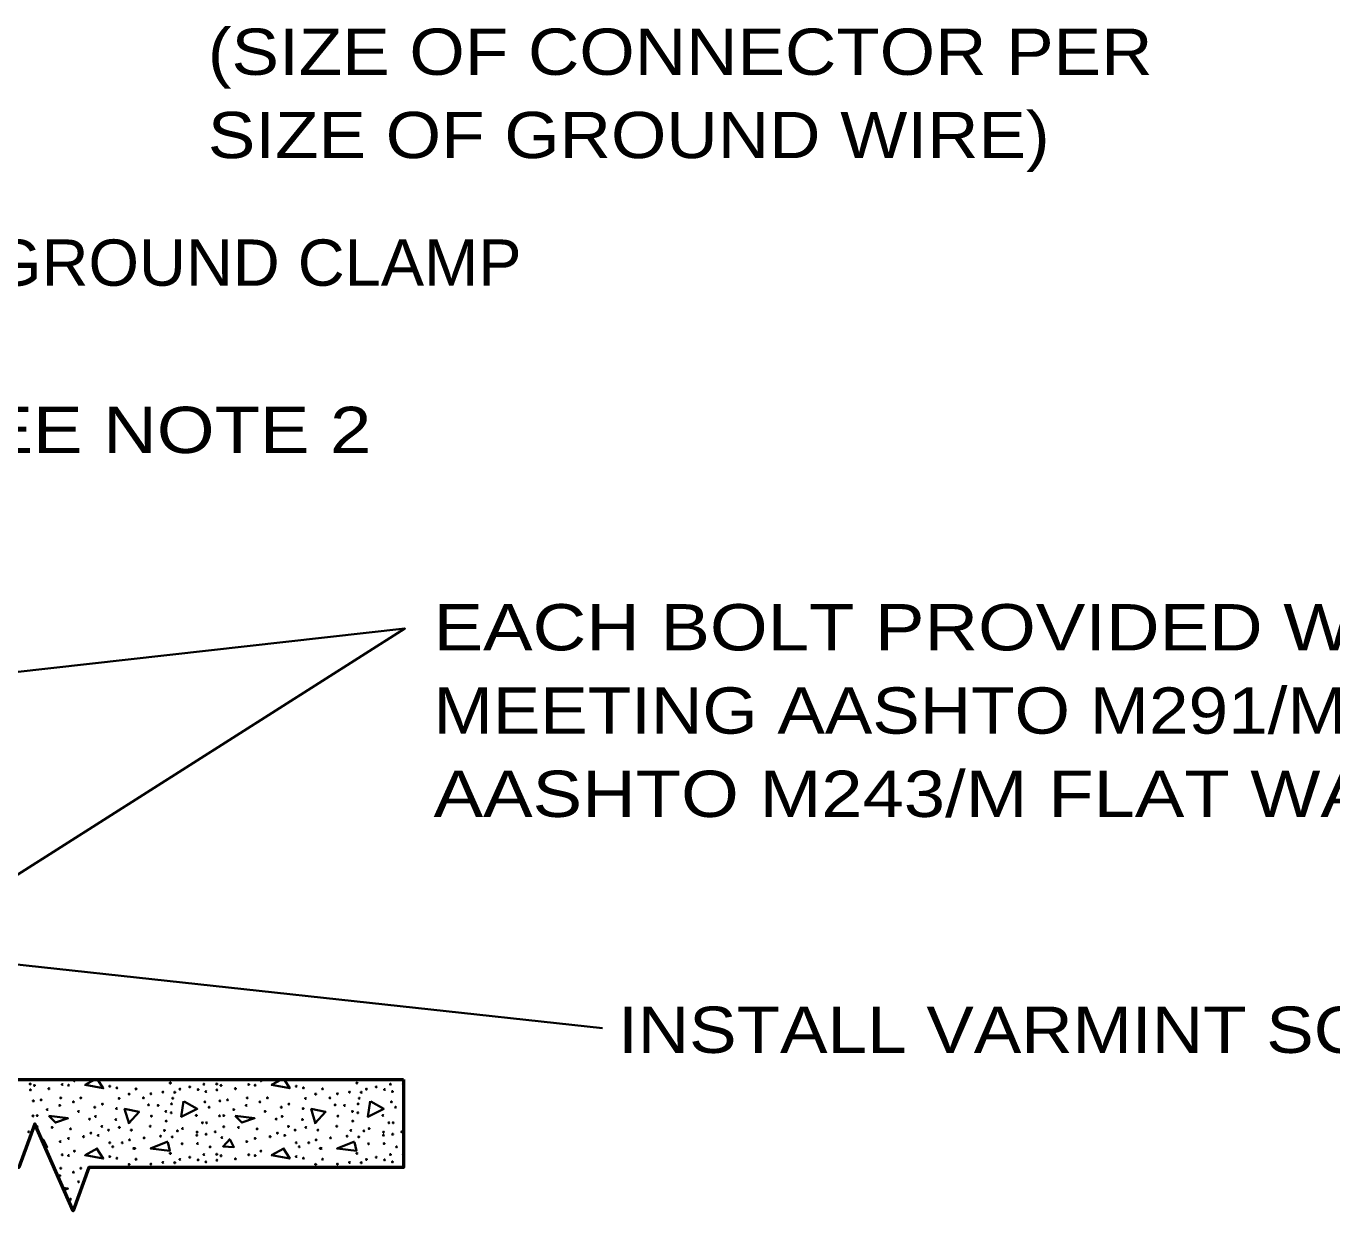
# Model space of a CAD drawing. Extents: x -24 to 689, y -7 to 446.
# Drawn here: x 464.1 to 534.7, y 233.6 to 297.7 of the extents above; entities that cross this region are included whole.
import ezdxf
from ezdxf.enums import TextEntityAlignment as Align

# ---------------------------------------------------------------- set-up
doc = ezdxf.new("R2010")
doc.units = 0
doc.layers.add('1', color=7, linetype='Continuous', lineweight=35)

msp = doc.modelspace()

# ---------------------------------------------------------------- linework, layer by layer
at = {"layer": '1'}
for p, q in [((460.988, 247.244), (495.251, 243.524)), ((465.041, 237.532), (464.96, 237.447))]:
    msp.add_line(p, q, dxfattribs=at)
at = {"layer": '1', "lineweight": 53}
msp.add_line((460.988, 240.744), (484.488, 240.744), dxfattribs=at)
at = {"layer": '1'}
for points in [[(458.988, 262.245), (484.563, 265.111), (458.988, 248.869)], [(467.818, 240.744), (467.281, 240.452), (468.261, 240.272), (467.957, 240.744)], [(471.405, 240.744), (471.861, 240.692), (471.85, 240.744)], [(477.898, 240.744), (477.361, 240.452), (478.341, 240.272), (478.037, 240.744)], [(481.485, 240.744), (481.941, 240.692), (481.93, 240.744)], [(472.641, 239.552), (473.341, 239.152), (472.481, 238.732), (472.601, 239.572)], [(482.721, 239.552), (483.421, 239.152), (482.561, 238.732), (482.681, 239.572)], [(469.661, 238.352), (469.421, 239.152), (470.201, 238.992), (469.641, 238.392)], [(479.741, 238.352), (479.501, 239.152), (480.281, 238.992), (479.721, 238.392)], [(465.113, 237.101), (465.241, 237.092), (465.041, 237.492)], [(471.761, 237.392), (470.821, 237.012), (471.861, 236.892), (471.761, 237.352)], [(475.121, 237.532), (474.741, 237.132), (475.321, 237.092), (475.121, 237.492)], [(481.841, 237.392), (480.901, 237.012), (481.941, 236.892), (481.841, 237.352)], [(467.941, 237.012), (467.281, 236.652), (468.261, 236.472), (467.901, 237.032)], [(478.021, 237.012), (477.361, 236.652), (478.341, 236.472), (477.981, 237.032)], [(466.089, 234.883), (466.361, 234.852), (466.137, 234.773)]]:
    msp.add_lwpolyline(points, dxfattribs=at)
at = {"layer": '1', "lineweight": 53}
msp.add_lwpolyline([(484.488, 240.744), (484.488, 235.994), (467.488, 235.994), (466.633, 233.645), (464.565, 238.344), (463.71, 235.994), (430.238, 235.994), (426.738, 235.994), (381.267, 235.994), (380.412, 233.645), (378.344, 238.344), (377.488, 235.994), (360.488, 235.994)], dxfattribs=at)
at = {"layer": '1'}
for points in [[(465.321, 238.772), (466.361, 238.652), (465.681, 238.412)], [(475.401, 238.772), (476.441, 238.652), (475.761, 238.412)]]:
    msp.add_lwpolyline(points, close=True, dxfattribs=at)
for centre in [(466.707, 240.673), (476.787, 240.673), (464.314, 240.501), (464.327, 240.183), (464.547, 240.421), (465.329, 240.249), (466.045, 240.474), (466.389, 240.435), (468.616, 240.382), (469, 240.289), (469.663, 239.957), (470.034, 240.236), (470.842, 239.971), (471.492, 240.063), (471.889, 240.554), (472.128, 240.05), (472.406, 240.222), (472.936, 240.342), (473.387, 240.196), (473.705, 240.488), (473.811, 240.09), (474.394, 240.501), (474.407, 240.183), (474.627, 240.421), (475.409, 240.249), (476.125, 240.474), (476.469, 240.435), (478.696, 240.382), (479.08, 240.289), (479.743, 239.957), (480.114, 240.236), (480.922, 239.971), (481.572, 240.063), (481.969, 240.554), (482.208, 240.05), (482.486, 240.222), (483.016, 240.342), (483.467, 240.196), (483.785, 240.488), (483.891, 240.09), (464.486, 239.586), (464.905, 239.639), (465.912, 239.347), (465.965, 239.745), (466.654, 239.533), (467.052, 239.745), (467.807, 239.241), (468.218, 239.414), (469.119, 239.719), (470.431, 239.745), (470.71, 239.374), (471.227, 239.347), (471.956, 239.427), (472.022, 239.732), (473.758, 239.533), (473.983, 239.241), (474.566, 239.586), (474.985, 239.639), (475.992, 239.347), (476.045, 239.745), (476.734, 239.533), (477.132, 239.745), (477.887, 239.241), (478.298, 239.414), (479.199, 239.719), (480.511, 239.745), (480.79, 239.374), (481.307, 239.347), (482.036, 239.427), (482.102, 239.732), (483.838, 239.533), (484.063, 239.241), (464.467, 238.775), (464.693, 238.791), (465.236, 239.122), (466.933, 239.016), (467.529, 238.605), (467.847, 238.751), (468.947, 238.579), (468.987, 239.175), (470.869, 238.764), (471.651, 239.016), (471.664, 238.499), (471.942, 238.95), (473.294, 238.804), (474.547, 238.775), (474.773, 238.791), (475.316, 239.122), (477.013, 239.016), (477.609, 238.605), (477.927, 238.751), (479.027, 238.579), (479.067, 239.175), (480.949, 238.764), (481.731, 239.016), (481.744, 238.499), (482.022, 238.95), (483.374, 238.804), (464.235, 237.916), (464.693, 238.194), (465.501, 238.154), (466.495, 238.075), (467.595, 237.849), (468.192, 238.207), (468.55, 238.008), (469.133, 238.154), (469.782, 238.008), (470.803, 238.221), (471.571, 237.995), (472.274, 237.969), (472.552, 238.088), (473.334, 237.902), (473.625, 238.406), (473.824, 237.788), (473.851, 238.406), (474.315, 237.916), (474.773, 238.194), (475.581, 238.154), (476.575, 238.075), (477.675, 237.849), (478.272, 238.207), (478.63, 238.008), (479.213, 238.154), (479.862, 238.008), (480.883, 238.221), (481.651, 237.995), (482.354, 237.969), (482.632, 238.088), (483.414, 237.902), (483.705, 238.406), (483.904, 237.788), (483.931, 238.406), (484.395, 237.916), (465.939, 237.39), (466.389, 237.563), (467.198, 237.655), (467.993, 237.722), (468.616, 237.324), (468.775, 237.112), (469.292, 237.324), (469.689, 237.483), (470.471, 237.589), (471.359, 237.682), (471.995, 237.642), (472.525, 237.271), (473.321, 237.735), (473.36, 237.284), (474.036, 237.099), (474.68, 237.602), (476.019, 237.39), (476.469, 237.563), (477.278, 237.655), (478.073, 237.722), (478.696, 237.324), (478.855, 237.112), (479.372, 237.324), (479.769, 237.483), (480.551, 237.589), (481.439, 237.682), (482.075, 237.642), (482.605, 237.271), (483.401, 237.735), (483.44, 237.284), (484.116, 237.099), (466.045, 236.674), (466.389, 236.635), (466.707, 236.873), (468.616, 236.582), (469, 236.489), (469.915, 237.019), (469.968, 237.019), (470.034, 236.436), (471.889, 236.754), (472.406, 236.422), (472.936, 236.542), (473.387, 236.396), (473.705, 236.688), (474.394, 236.701), (474.407, 236.383), (474.627, 236.621), (475.409, 236.449), (476.125, 236.674), (476.469, 236.635), (476.787, 236.873), (478.696, 236.582), (479.08, 236.489), (479.995, 237.019), (480.048, 237.019), (480.114, 236.436), (481.969, 236.754), (482.486, 236.422), (483.016, 236.542), (483.467, 236.396), (483.785, 236.688), (465.965, 235.945), (466.654, 235.733), (467.052, 235.945), (469.663, 236.157), (470.842, 236.171), (471.492, 236.263), (472.128, 236.25), (473.811, 236.29), (479.743, 236.157), (480.922, 236.171), (481.572, 236.263), (482.208, 236.25), (483.891, 236.29), (465.912, 235.547), (466.933, 235.216), (466.495, 234.275)]:
    msp.add_circle(centre, 0.0265, dxfattribs=at)
for centre, start, end in [((484.474, 240.501), 57.21077, 302.78922), ((484.487, 240.183), 87.52764, 272.47236), ((484.474, 236.701), 57.21077, 302.78922), ((484.487, 236.383), 87.52764, 272.47236)]:
    msp.add_arc(centre, 0.0265, start, end, dxfattribs=at)

# ---------------------------------------------------------------- texts
for s, width, p in [('(SIZE OF CONNECTOR PER', 1.15, (473.916, 295.027)), ('SIZE OF GROUND WIRE)', 1.15, (473.916, 290.527)), ('EACH BOLT PROVIDED WITH TWO HEX NUTS', 1.2, (486.114, 263.93)), ('MEETING AASHTO M291/M, GRADE A AND TWO', 1.15, (486.114, 259.43)), ('AASHTO M243/M FLAT WASHERS.', 1.2, (486.114, 254.93))]:
    msp.add_text(s, height=2.5, dxfattribs=dict(at, width=width)).set_placement(p)
for s, width, p in [('GROUND CLAMP', 1.05, (476.534, 283.632)), ('SEE NOTE 2', 1.2, (470.935, 274.593)), ('INSTALL VARMINT SCREEN', 1.15, (521.609, 242.181))]:
    msp.add_text(s, height=2.5, dxfattribs=dict(at, width=width)).set_placement(p, align=Align.CENTER)

doc.saveas('drawing.dxf')
